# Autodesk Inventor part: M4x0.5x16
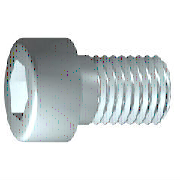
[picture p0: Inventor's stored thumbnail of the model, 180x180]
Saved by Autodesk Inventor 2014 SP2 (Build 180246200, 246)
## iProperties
Created: 2014-07
Part Number: M4x0.5x16
Material: 강, 연강
Description: 6각머리 태핑 나사
Document SubType Name: Modeling
Standard: KS B 1003
Designer: KYOUNG IL JANG
Standards Organization: KS
Language: ko-KR
Size Designation: M 4 x 16
Categories: <MemberInstance><Categories><Category DisplayName="조임쇠" InternalName="e4da775c-781d-43d5-af7c-5136215cf5a6" Mnemonic="FSTN"><Category DisplayName="볼트" InternalN
Density: 1 g/cm^3
Appearance: 강철
Company: 한국ATC센터
IsCustomPart: 1
Author: KYOUNG IL JANG
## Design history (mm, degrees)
sketch "스케치1"
  geometry: L1 (-1, 0)-(16, 0); L2 (16, 0)-(16, 2); L3 (16, 2)-(1.75, 2); L4 (1.75, 2)-(1.32, 2); L5 (1.32, 2)-(0, 2); L6 (0, 2)-(0, 3.5); L7 (0, 3.5)-(-4, 3.5); L8 (-4, 3.5)-(-4, 1.732); L9 (-4, 1.732)-(-2, 1.732); L10 (-2, 1.732)-(-1, 0); L11 (-8, 0)-(20, 0) reference; L12 (0, -0.7)-(0, 4.2) reference; L13 (1.75, 2)-(0, 2)
  constraints: 22 end point, 6 parallel, 2 collinear, 2 perpendicular, 1 horizontal, 1 point on line
  dimensions: "d1" = 14.25 distance from line of L3.end L2 (= GEL); "d2" = 0.42952 distance of L4.end L3.end (computed from GAL); "d3" = 4 distance between parallel lines of L8 L6 (= KOH); "d4" = 2 distance of L8.end L9.end (= INTI); "d5" = 60 deg angle of L10 L1; "d6" = 4 diameter of L3 L1 (= GD); "d7" = 4 diameter of L5 L1 (= BDM); "d8" = 3.4641 diameter of L9 L1 (= 1.1547 x SW); "d9" = 7 diameter of L7 L1 (= KOD); "d26" = 16 distance between parallel lines of L12 L2 (= NLG)
revolve "본체" sketch "스케치1" stored, may be unused: angle "d10" = 90 deg
sketch "스케치2"
  geometry: L1 (0, -4.9)-(0, 4.9) reference; L2 (-4.9, 0)-(4.9, 0) reference; L3 (1.732, 0)-(0.866, -1.5); L4 (0.866, -1.5)-(-0.866, -1.5); L5 (-0.866, -1.5)-(-1.732, 0); L6 (-1.732, 0)-(-0.866, 1.5); L7 (-0.866, 1.5)-(0.866, 1.5); L8 (0.866, 1.5)-(1.732, 0); 2 further points
  constraints: 12 end point, 1 coincident, 1 horizontal alignment, 1 point on line, 12 other
extrude "슬롯" join sketch "스케치2" stored distance "d11" = 10; taper "d12" = 0 deg
workplane "Work Plane1"
fillet "Fillet2" dims "d30" = 0.1 (= R)
body "Solid1"
fillet "모깎기1" dims "d17" = 0.4 (= RR)
feature "스레드" dims "d13" = 14.25 (= GEL), "d14" = 0
chamfer "모따기1" distance "d15" = 0.42941 (= -0.5 x SPD + 0.5 x GD); stored, may be unused: second distance "d16" = 0.42941 (= GUL), angle "d27" = 45 deg
other parameters: "GD" = 4 (= NND) [user parameter; used in 2 equation terms], "NLG" = 16 [user parameter; used in 1 equation term], "GEL" = 14.25 [user parameter; used in 2 equation terms], "KOD" = 7 [user parameter; used in 1 equation term], "KOH" = 4 [user parameter; used in 1 equation term], "INTI" = 2 [user parameter; used in 1 equation term], "GAL" = 0.42941 (= 0.61345 x PTC) [user parameter; used in 1 equation term], "GUL" = 0.42941 (= 0.61345 x PTC) [user parameter; used in 1 equation term], "BDM" = 4 (= NND) [user parameter; used in 1 equation term], "SW" = 3 [user parameter; used in 2 equation terms], "RR" = 0.4 [user parameter; used in 1 equation term], "SPD" = 3.14117 (= NND - 1.2269 x PTC) [user parameter; used in 1 equation term], "d19" = 0, "d28" = 0, "d29" = 0, "R" = 0.1 [user parameter; used in 1 equation term], "PHH" = 0.2 [user parameter], "GD1" = 3.14117 (= THREADDIA - 1.2269 x PTC) [user parameter], "THREADDIA" = 4 [user parameter; used in 1 equation term], "FAWI" = 45 deg [user parameter], "TPU" = 14.28571 (computed from PTC) [user parameter], "PTC" = 0.7 [user parameter; used in 5 equation terms], "NND" = 4 [user parameter; used in 3 equation terms], "TOA" = 30 deg [user parameter], "E0" = 3.465 (= 1.155 x SW) [user parameter]
